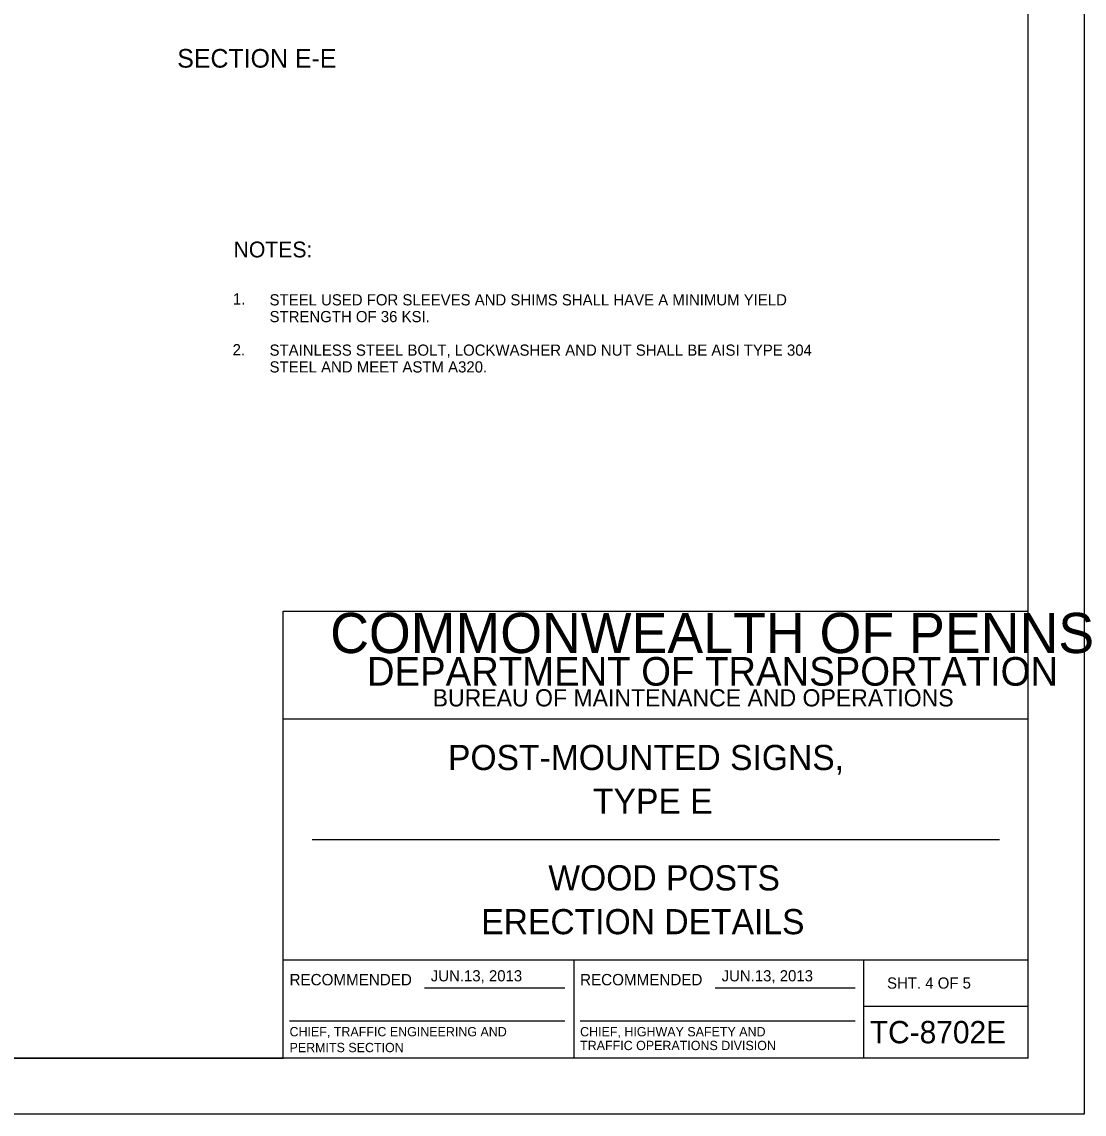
# Model space of a CAD drawing. Extents: x -2340 to 628, y -879 to 309.
# Drawn here: x -1402.6 to -1117.4, y -878.6 to -585.4 of the extents above; entities that cross this region are included whole.
import ezdxf

# ---------------------------------------------------------------- set-up
doc = ezdxf.new("R2010")
doc.units = 0
for name, color, linetype in [('Level 1', 7, 'Continuous'), ('Level 2', 7, 'Continuous'), ('Level 3', 7, 'Continuous'), ('Level 4', 7, 'Continuous'), ('PLT-BNDY', 7, 'Continuous')]:
    doc.layers.add(name, color=color, linetype=linetype)

msp = doc.modelspace()

# ---------------------------------------------------------------- linework, layer by layer
at = {"layer": 'Level 1'}
for p, q in [((-1132.39, -863.56), (-1132.39, -299.56)), ((-1332.39, -863.56), (-1332.39, -743.56)), ((-1332.39, -743.56), (-1132.39, -743.56)), ((-1132.39, -772.56), (-1332.39, -772.56)), ((-1324.64, -804.88), (-1140.14, -804.88)), ((-1332.39, -837.19), (-1132.39, -837.19)), ((-1254.39, -837.19), (-1254.39, -863.56)), ((-1176.51, -863.56), (-1176.51, -837.19)), ((-1294.45, -844.62), (-1256.83, -844.62)), ((-1216.45, -844.62), (-1178.83, -844.62)), ((-1176.51, -849.56), (-1132.39, -849.56)), ((-1330.7, -853.51), (-1256.83, -853.51)), ((-1252.7, -853.51), (-1178.83, -853.51)), ((-1132.39, -863.56), (-1918.39, -863.56)), ((-1918.39, -863.56), (-1332.39, -863.56))]:
    msp.add_line(p, q, dxfattribs=at)
at = {"layer": 'PLT-BNDY'}
msp.add_lwpolyline([(-1958.39, -284.56), (-1117.39, -284.56), (-1117.39, -878.56), (-1958.39, -878.56)], close=True, dxfattribs=at)

# ---------------------------------------------------------------- texts
at = {"layer": 'Level 1'}
for s, height, p in [('COMMONWEALTH OF PENNSYLVANIA', 10.7827, (-1319.79, -754.83)), ('DEPARTMENT OF TRANSPORTATION', 7.6838, (-1309.93, -763.58)), ('BUREAU OF MAINTENANCE AND OPERATIONS', 4.6252, (-1292.29, -769.15)), ('POST-MOUNTED SIGNS,', 6.75, (-1288.16, -786.22)), ('TYPE E', 6.75, (-1249.23, -797.97)), ('WOOD POSTS', 6.75, (-1261.23, -818.53)), ('ERECTION DETAILS', 6.75, (-1279.23, -830.28)), ('RECOMMENDED', 3.048, (-1330.7, -843.99)), ('RECOMMENDED', 3.048, (-1252.7, -843.99)), ('SHT. 4 OF 5', 3, (-1170.3, -844.88)), ('CHIEF, TRAFFIC ENGINEERING AND', 2.5, (-1330.7, -857.68)), ('CHIEF, HIGHWAY SAFETY AND', 2.5, (-1252.7, -857.68)), ('TC-8702E', 6, (-1174.91, -859.56)), ('TRAFFIC OPERATIONS DIVISION', 2.5, (-1252.7, -861.38)), ('PERMITS SECTION', 2.5, (-1330.7, -861.93))]:
    msp.add_text(s, height=height, dxfattribs=at).set_placement(p)
at = {"layer": 'Level 2'}
for s, height, p in [('SECTION E-E', 5, (-1360.84, -597.72)), ('JUN.13, 2013', 3, (-1292.78, -842.93)), ('JUN.13, 2013', 3, (-1214.71, -842.93))]:
    msp.add_text(s, height=height, dxfattribs=at).set_placement(p)
at = {"layer": 'Level 3'}
msp.add_text('NOTES:', height=4.25, dxfattribs=at).set_placement((-1345.72, -648.65))
at = {"layer": 'Level 4'}
for s, p in [('1.', (-1345.92, -661.29)), ('STEEL USED FOR SLEEVES AND SHIMS SHALL HAVE A MINIMUM YIELD', (-1336.06, -661.53)), ('STRENGTH OF 36 KSI.', (-1336.06, -666.03)), ('2.', (-1345.98, -674.92)), ('STAINLESS STEEL BOLT, LOCKWASHER AND NUT SHALL BE AISI TYPE 304', (-1336.06, -675.03)), ('STEEL AND MEET ASTM A320.', (-1336.06, -679.53))]:
    msp.add_text(s, height=3, dxfattribs=at).set_placement(p)

doc.saveas('drawing.dxf')
